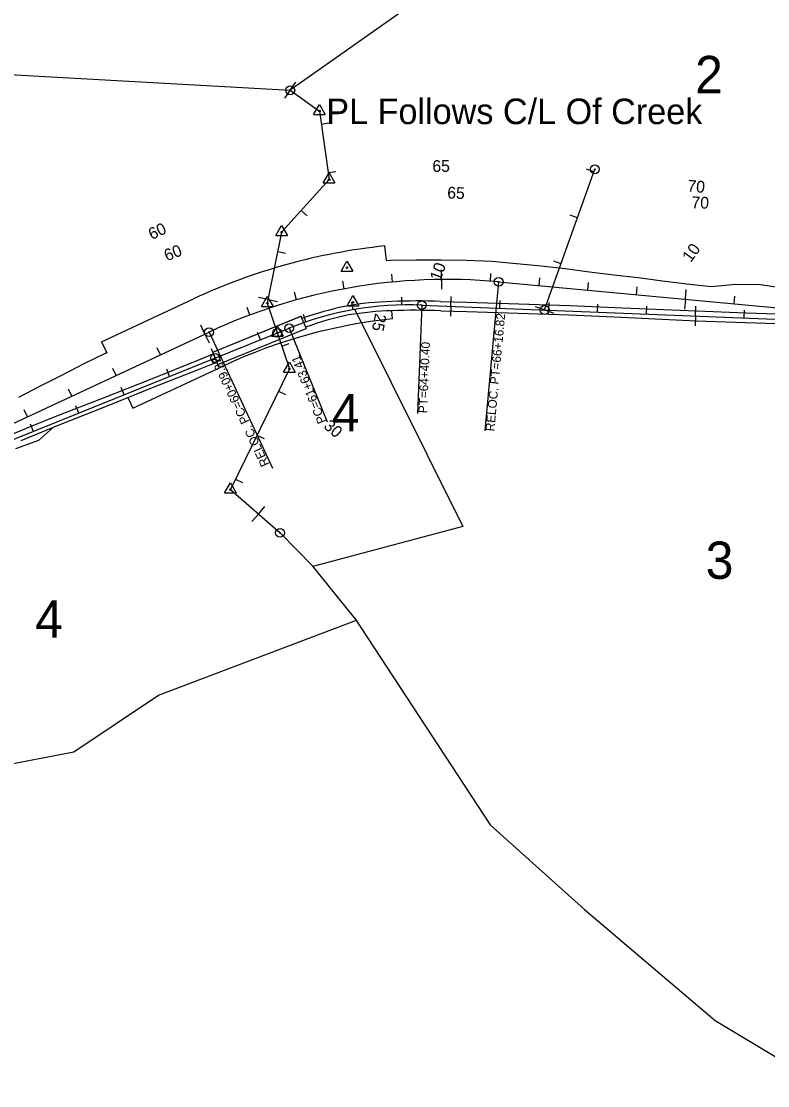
# Model space of a CAD drawing. Extents: x 1965308 to 1970456, y 1116335 to 1119906.
# Drawn here: x 1967302 to 1968827, y 1116335 to 1118511 of the extents above; entities that cross this region are included whole.
import ezdxf

# ---------------------------------------------------------------- set-up
doc = ezdxf.new("R2010")
doc.units = 0
for name, color, linetype in [('RD_EX_Bridge', 7, 'Continuous'), ('RD_EX_DV_Prop', 7, 'Continuous'), ('RD_EX_DV_TX_Prop', 7, 'Continuous'), ('RD_EX_Road', 7, 'Continuous'), ('RD_EX_RW', 7, 'Continuous'), ('RD_HC_Cl', 7, 'Continuous'), ('RD_HC_CL_Rel', 7, 'Continuous'), ('RD_HC_Data', 7, 'Continuous'), ('RD_HC_Data_Rel', 7, 'Continuous'), ('RD_HC_Data_Tic', 7, 'Continuous'), ('RD_HC_Data_Tic_Rel', 7, 'Continuous'), ('RD_HC_TX_Rel_Sta50', 7, 'Continuous'), ('RD_HC_TX_StaOther', 7, 'Continuous'), ('RD_PD_RW', 7, 'Continuous'), ('RD_SMD_Locator', 7, 'Continuous')]:
    doc.layers.add(name, color=color, linetype=linetype)

msp = doc.modelspace()

# ---------------------------------------------------------------- linework, layer by layer
at = {"layer": 'RD_EX_Bridge'}
for p, q in [((1967693.2, 1117834.7), (1967873.6, 1117908.4)), ((1967873.6, 1117908.4), (1967884, 1117883.1)), ((1967703.5, 1117809.4), (1967884, 1117883.1)), ((1967693.2, 1117834.7), (1967703.5, 1117809.4))]:
    msp.add_line(p, q, dxfattribs=at)
at = {"layer": 'RD_EX_DV_Prop'}
for p, q in [((1970021.7, 1119906.4), (1967851.7, 1118370.2)), ((1965856.7, 1118481.4), (1967851.7, 1118370.2)), ((1967983.3, 1117921.8), (1968204.3, 1117478.1)), ((1967830.8, 1117465.4), (1967898.1, 1117396.8)), ((1968204.3, 1117478.1), (1967897.6, 1117396.5)), ((1967983, 1117291.4), (1967898.1, 1117396.8)), ((1967983, 1117291.4), (1968260.1, 1116868.2)), ((1967986.9, 1117286.5), (1967983, 1117291.4)), ((1967582.6, 1117133.3), (1967962.1, 1117277.1)), ((1967962.1, 1117277.1), (1967986.9, 1117286.5)), ((1967409.3, 1117017.8), (1967582.6, 1117133.3)), ((1967101.3, 1116957.5), (1967409.3, 1117017.8)), ((1968260.1, 1116868.2), (1968452.8, 1116695.3)), ((1968452.8, 1116695.3), (1968719.5, 1116468.1)), ((1968719.5, 1116468.1), (1968941.8, 1116334.8))]:
    msp.add_line(p, q, dxfattribs=at)
at = {"layer": 'RD_EX_Road'}
for points in [[(1968158.7, 1117938.6), (1968212.1, 1117937.2), (1968318.8, 1117933.3), (1968422.8, 1117929.9), (1968530.5, 1117925.7)], [(1968530.5, 1117925.7), (1968682, 1117919), (1968783.2, 1117915.4), (1968888.6, 1117911.4), (1968991.2, 1117907.1), (1969092, 1117903.1), (1969191.1, 1117898.7), (1969283.3, 1117895.4)], [(1968159.2, 1117919.4), (1968212.5, 1117918), (1968317.5, 1117914.4), (1968421.5, 1117910.8), (1968527.8, 1117906.4)], [(1968527.8, 1117906.4), (1968680.8, 1117899.1), (1968781.7, 1117895.4), (1968887.9, 1117891.8), (1968988.7, 1117888.2), (1969090.1, 1117882.8), (1969189.3, 1117879), (1969282.9, 1117875.4)], [(1966769.5, 1117457.5), (1966870.2, 1117497.3), (1966971.2, 1117539), (1967071.1, 1117580.2), (1967172.6, 1117621.5), (1967270.8, 1117661.7), (1967321.1, 1117682.6), (1967371.5, 1117702.9), (1967470.3, 1117741.6), (1967566.7, 1117779.5), (1967661.2, 1117817.5), (1967694.4, 1117831.2)], [(1967302.2, 1117654.1), (1967379.3, 1117686.2), (1967476.1, 1117724.4), (1967573.9, 1117763.5), (1967667.7, 1117800.7), (1967701.6, 1117814)]]:
    msp.add_lwpolyline(points, dxfattribs=at)
for centre, radius, start, end in [((1968104.9, 1117261.1), 682.1, 101.7162, 109.6396), ((1968075.1, 1117320.6), 617.9, 91.4965, 100.1295), ((1968111.4, 1116608.6), 1330.8, 87.9632, 92.259), ((1968107.6, 1116504.3), 1416, 87.9115, 91.9598), ((1968080.6, 1117363), 558.7, 101.3479, 110.7006), ((1968080.7, 1117246.5), 673.3, 91.837, 99.4057)]:
    msp.add_arc(centre, radius, start, end, dxfattribs=at)
at = {"layer": 'RD_EX_RW'}
for p, q in [((1967693.2, 1117834.7), (1967873.9, 1117908.5)), ((1967875.7, 1117903.5), (1967873.9, 1117908.5)), ((1967703.5, 1117809.4), (1967884, 1117883.1)), ((1967883.1, 1117885.6), (1967884, 1117883.1)), ((1967694.6, 1117831.3), (1967693.2, 1117834.7)), ((1967701.6, 1117814), (1967703.5, 1117809.4))]:
    msp.add_line(p, q, dxfattribs=at)
for points in [[(1968059, 1117938.4), (1968058.9, 1117938.4), (1968058.9, 1117938.4)], [(1968158.7, 1117938.6), (1968212.1, 1117937.2), (1968318.8, 1117933.3), (1968422.8, 1117929.9), (1968530.5, 1117925.7)], [(1968530.5, 1117925.7), (1968682, 1117919), (1968783.2, 1117915.4), (1968888.6, 1117911.4), (1968991.2, 1117907.1), (1969092, 1117903.1), (1969191.1, 1117898.7), (1969283.3, 1117895.4)], [(1967970.6, 1117910.8), (1967970.7, 1117910.8), (1967970.8, 1117910.8)], [(1968159.2, 1117919.4), (1968212.5, 1117918), (1968317.5, 1117914.4), (1968421.5, 1117910.8), (1968527.8, 1117906.4)], [(1968527.8, 1117906.4), (1968680.8, 1117899.1), (1968781.7, 1117895.4), (1968887.9, 1117891.8), (1968988.7, 1117888.2), (1969090.1, 1117882.8), (1969189.3, 1117879), (1969282.9, 1117875.4)], [(1966769.5, 1117457.5), (1966870.2, 1117497.3), (1966971.2, 1117539), (1967071.1, 1117580.2), (1967172.6, 1117621.5), (1967270.8, 1117661.7), (1967321.1, 1117682.6), (1967371.5, 1117702.9), (1967470.3, 1117741.6), (1967566.7, 1117779.5), (1967661.2, 1117817.5), (1967694.6, 1117831.3)], [(1967302.2, 1117654.1), (1967379.3, 1117686.2), (1967476.1, 1117724.4), (1967573.9, 1117763.5), (1967667.7, 1117800.7), (1967701.6, 1117814)]]:
    msp.add_lwpolyline(points, dxfattribs=at)
for centre, radius, start, end in [((1968104.9, 1117261.1), 682.1, 101.7162, 109.6396), ((1968075.1, 1117320.6), 617.9, 91.4996, 100.1295), ((1968111.4, 1116608.6), 1330.8, 87.9632, 92.2576), ((1968107.6, 1116504.3), 1416, 87.9115, 91.9598), ((1968080.6, 1117363), 558.7, 101.3567, 110.7006), ((1968080.7, 1117246.5), 673.3, 91.837, 99.3984)]:
    msp.add_arc(centre, radius, start, end, dxfattribs=at)
at = {"layer": 'RD_HC_Cl'}
for p, q in [((1967851.7, 1118370.2), (1967911.4, 1118327.7)), ((1967911.4, 1118327.7), (1967931.1, 1118187.5)), ((1968371.4, 1117921), (1968474, 1118208.6)), ((1967931.1, 1118187.5), (1967834, 1118080)), ((1967834, 1118080), (1967804.8, 1117934.9)), ((1967804.8, 1117934.9), (1967849.8, 1117800.6)), ((1968120.3, 1117930.9), (1969279, 1117884.9)), ((1966770.7, 1117448.1), (1967849.5, 1117883.9)), ((1967849.8, 1117800.6), (1967729.3, 1117553.7)), ((1967729.3, 1117553.7), (1967830.8, 1117465.4))]:
    msp.add_line(p, q, dxfattribs=at)
msp.add_arc((1968094.4, 1117277.5), 653.9, 87.7266, 111.9958, dxfattribs=at)
at = {"layer": 'RD_HC_CL_Rel'}
for p, q in [((1968277.4, 1117978.5), (1969226.4, 1117889.9)), ((1966858.9, 1117489.3), (1967685.7, 1117875.7))]:
    msp.add_line(p, q, dxfattribs=at)
msp.add_arc((1968170.8, 1116837.5), 1145.9, 84.6661, 115.0463, dxfattribs=at)
at = {"layer": 'RD_HC_Data'}
for p, q in [((1967899.5, 1118320.8), (1967911.4, 1118341.4)), ((1967911.4, 1118341.4), (1967923.3, 1118320.8)), ((1967899.5, 1118320.8), (1967923.3, 1118320.8)), ((1967919.1, 1118180.7), (1967931.1, 1118201.3)), ((1967931.1, 1118201.3), (1967943, 1118180.7)), ((1967919.1, 1118180.7), (1967943, 1118180.7)), ((1967822.1, 1118073.1), (1967834, 1118093.7)), ((1967822.1, 1118073.1), (1967845.9, 1118073.1)), ((1967834, 1118093.7), (1967845.9, 1118073.1)), ((1967792.9, 1117928), (1967804.8, 1117948.6)), ((1967804.8, 1117948.6), (1967816.7, 1117928)), ((1967967.9, 1117929.6), (1967979.8, 1117950.3)), ((1967979.8, 1117950.3), (1967991.7, 1117929.6)), ((1967792.9, 1117928), (1967816.7, 1117928)), ((1967967.9, 1117929.6), (1967991.7, 1117929.6)), ((1968120.3, 1117930.9), (1968111.5, 1117709)), ((1967813.3, 1117867.2), (1967825.2, 1117887.8)), ((1967825.2, 1117887.8), (1967837.1, 1117867.2)), ((1967849.5, 1117883.9), (1967926.8, 1117692.4)), ((1967813.3, 1117867.2), (1967837.1, 1117867.2)), ((1967837.9, 1117793.7), (1967849.8, 1117814.4)), ((1967849.8, 1117814.4), (1967861.7, 1117793.7)), ((1967837.9, 1117793.7), (1967861.7, 1117793.7)), ((1967717.4, 1117546.8), (1967729.3, 1117567.4)), ((1967729.3, 1117567.4), (1967741.2, 1117546.8)), ((1967717.4, 1117546.8), (1967741.2, 1117546.8))]:
    msp.add_line(p, q, dxfattribs=at)
for centre, radius in [((1967851.7, 1118370.2), 9), ((1967851.7, 1118370.2), 0.845), ((1967911.4, 1118327.7), 1.59), ((1968474, 1118208.6), 9), ((1968474, 1118208.6), 0.845), ((1967931.1, 1118187.5), 1.59), ((1967834, 1118080), 1.59), ((1967804.8, 1117934.9), 1.59), ((1967979.8, 1117936.5), 1.59), ((1968120.3, 1117930.9), 9), ((1968120.3, 1117930.9), 0.845), ((1968371.4, 1117921), 9), ((1968371.4, 1117921), 9), ((1968371.4, 1117921), 0.845), ((1968371.4, 1117921), 0.845), ((1967825.2, 1117874.1), 9), ((1967849.5, 1117883.9), 9), ((1967849.5, 1117883.9), 0.845), ((1967825.2, 1117874.1), 1.59), ((1967825.2, 1117874.1), 0.845), ((1967698.1, 1117822.7), 9), ((1967698.1, 1117822.7), 0.845), ((1967849.8, 1117800.6), 1.59), ((1967729.3, 1117553.7), 1.59), ((1967830.8, 1117465.4), 9), ((1967830.8, 1117465.4), 0.845)]:
    msp.add_circle(centre, radius, dxfattribs=at)
at = {"layer": 'RD_HC_Data_Rel'}
for p, q in [((1967955.7, 1118000.5), (1967967.6, 1118021.1)), ((1967967.6, 1118021.1), (1967979.5, 1118000.5)), ((1967955.7, 1118000.5), (1967979.5, 1118000.5)), ((1968277.4, 1117978.5), (1968248.9, 1117674.2)), ((1967685.7, 1117875.7), (1967815.6, 1117597.7))]:
    msp.add_line(p, q, dxfattribs=at)
for centre, radius in [((1967967.6, 1118007.4), 1.59), ((1968277.4, 1117978.5), 9), ((1968277.4, 1117978.5), 0.845), ((1967685.7, 1117875.7), 9), ((1967685.7, 1117875.7), 0.845)]:
    msp.add_circle(centre, radius, dxfattribs=at)
at = {"layer": 'RD_HC_Data_Tic'}
for p, q in [((1967851.7, 1118370.2), (1967863.4, 1118386.5)), ((1967851.7, 1118370.2), (1967840.1, 1118354)), ((1967915.1, 1118301.2), (1967930.9, 1118303.4)), ((1967929, 1118202.2), (1967944.8, 1118204.4)), ((1968472.1, 1118203.5), (1968457.1, 1118208.9)), ((1967874, 1118124.2), (1967885.9, 1118113.5)), ((1968438.5, 1118109.4), (1968423.5, 1118114.7)), ((1967826.1, 1118040.4), (1967841.7, 1118037.2)), ((1968404.9, 1118015.2), (1968389.9, 1118020.5)), ((1967806.3, 1117942.4), (1967786.7, 1117946.3)), ((1967806.3, 1117942.4), (1967825.9, 1117938.4)), ((1968079.9, 1117931.3), (1968079.6, 1117947.3)), ((1968179.9, 1117928.6), (1968180.7, 1117948.6)), ((1967980.5, 1117921.5), (1967977.7, 1117937.2)), ((1968179.9, 1117928.6), (1968179.1, 1117908.6)), ((1968279.8, 1117924.6), (1968280.4, 1117940.6)), ((1968371.4, 1117921), (1968352.5, 1117927.7)), ((1968371.4, 1117921), (1968390.2, 1117914.3)), ((1968379.7, 1117920.6), (1968380.4, 1117936.6)), ((1968479.6, 1117916.7), (1968480.3, 1117932.7)), ((1968579.6, 1117912.7), (1968580.2, 1117928.7)), ((1968679.5, 1117908.7), (1968680.3, 1117928.7)), ((1968779.4, 1117904.8), (1968780, 1117920.8)), ((1967883.8, 1117896.6), (1967878.6, 1117911.8)), ((1968679.5, 1117908.7), (1968678.7, 1117888.8)), ((1967790.7, 1117860.1), (1967784.7, 1117874.9)), ((1967698, 1117822.7), (1967690.5, 1117841.2)), ((1967834.2, 1117847.3), (1967849.3, 1117852.4)), ((1967698, 1117822.7), (1967705.4, 1117804.1)), ((1967605.2, 1117785.2), (1967599.2, 1117800)), ((1967512.5, 1117747.7), (1967506.5, 1117762.6)), ((1967827.6, 1117755), (1967841.9, 1117748)), ((1967419.8, 1117710.3), (1967413.8, 1117725.1)), ((1967327.1, 1117672.8), (1967321.1, 1117687.7)), ((1967783.7, 1117665.1), (1967798.1, 1117658.1)), ((1967739.8, 1117575.2), (1967754.2, 1117568.2)), ((1967786.6, 1117503.8), (1967799.8, 1117518.9)), ((1967786.6, 1117503.8), (1967773.5, 1117488.7))]:
    msp.add_line(p, q, dxfattribs=at)
at = {"layer": 'RD_HC_Data_Tic_Rel'}
for p, q in [((1968060.9, 1117978.1), (1968059.3, 1117994.1)), ((1968160.7, 1117983.4), (1968160.5, 1118003.4)), ((1968260.6, 1117979.9), (1968261.8, 1117995.9)), ((1968360.2, 1117970.7), (1968361.7, 1117986.7)), ((1967961.9, 1117964.2), (1967958.9, 1117979.9)), ((1968160.7, 1117983.4), (1968160.9, 1117963.4)), ((1968459.7, 1117961.4), (1968461.2, 1117977.4)), ((1968559.3, 1117952.1), (1968560.8, 1117968.1)), ((1967864.5, 1117941.7), (1967860.2, 1117957.1)), ((1968658.9, 1117942.8), (1968657, 1117922.9)), ((1968658.9, 1117942.8), (1968660.7, 1117962.8)), ((1968758.4, 1117933.5), (1968759.9, 1117949.5)), ((1967769.4, 1117910.8), (1967763.8, 1117925.8)), ((1967677.4, 1117871.8), (1967668.9, 1117889.9)), ((1967677.4, 1117871.8), (1967685.8, 1117853.7)), ((1967586.8, 1117829.4), (1967580, 1117843.9)), ((1967496.2, 1117787.1), (1967489.4, 1117801.6)), ((1967405.6, 1117744.8), (1967398.8, 1117759.3)), ((1967315, 1117702.4), (1967308.2, 1117716.9))]:
    msp.add_line(p, q, dxfattribs=at)
at = {"layer": 'RD_PD_RW'}
for p, q in [((1968048.3, 1118022.1), (1968045.2, 1118051.9)), ((1968048.3, 1118022.1), (1968056.6, 1118022.8)), ((1968056.6, 1118022.8), (1968108.6, 1118023.3)), ((1968108.6, 1118023.3), (1968160.3, 1118023.6)), ((1968160.3, 1118023.6), (1968212.1, 1118023)), ((1968212.1, 1118023), (1968263.8, 1118020.6)), ((1968263.8, 1118020.6), (1968314.2, 1118016.3)), ((1968314.2, 1118016.3), (1968364, 1118011.2)), ((1968364, 1118011.2), (1968413.7, 1118005.8)), ((1968413.7, 1118005.8), (1968463.3, 1117999.1)), ((1968463.3, 1117999.1), (1968512.9, 1117993.1)), ((1968512.9, 1117993.1), (1968562.6, 1117987.5)), ((1968562.6, 1117987.5), (1968612.2, 1117980.7)), ((1968612.2, 1117980.7), (1968661.8, 1117974.4)), ((1968661.8, 1117974.4), (1968711.4, 1117968.9)), ((1968711.4, 1117968.9), (1968762, 1117973.5)), ((1968762, 1117973.5), (1968812.3, 1117973.2)), ((1968812.3, 1117973.2), (1968861.9, 1117965.3)), ((1967466.2, 1117855.9), (1967654, 1117943.6)), ((1968060.6, 1117902.7), (1968058.9, 1117919.5)), ((1967466.2, 1117855.9), (1967476.8, 1117833.3)), ((1967475, 1117832.4), (1967476.8, 1117833.3)), ((1967475, 1117832.4), (1967430, 1117810.6)), ((1967430, 1117810.6), (1967385.5, 1117787.6)), ((1967529.7, 1117720), (1967717.5, 1117807.7)), ((1967385.5, 1117787.6), (1967340.9, 1117765)), ((1967340.9, 1117765), (1967296.4, 1117742.1)), ((1967519.5, 1117741.8), (1967529.7, 1117720)), ((1967367.7, 1117681.4), (1967337.6, 1117654.3)), ((1967337.6, 1117654.3), (1967290.1, 1117637.3))]:
    msp.add_line(p, q, dxfattribs=at)
for radius in [1220.9, 1070.9]:
    msp.add_arc((1968170.8, 1116837.5), radius, 95.9072, 115.0463, dxfattribs=at)
at = {"layer": 'RD_SMD_Locator'}
for centre in [(1967851.7, 1118370.2), (1967911.4, 1118327.7), (1968474, 1118208.6), (1967931.1, 1118187.5), (1967834, 1118080), (1967804.8, 1117934.9), (1967979.8, 1117936.5), (1968120.3, 1117930.9), (1968371.4, 1117921), (1968371.4, 1117921), (1967849.5, 1117883.9), (1967825.2, 1117874.1), (1967825.2, 1117874.1), (1967698.1, 1117822.7), (1967849.8, 1117800.6), (1967729.3, 1117553.7), (1967830.8, 1117465.4)]:
    msp.add_circle(centre, 0.003, dxfattribs=at)

# ---------------------------------------------------------------- texts
at = {"layer": 'RD_EX_DV_TX_Prop'}
for s, height, p in [('2', 76.4, (1968678.8, 1118364.1)), ('PL Follows C/L Of Creek', 52.212, (1967925.3, 1118301)), ('4', 76.4, (1967936.6, 1117673)), ('3', 76.4, (1968700.4, 1117371.1)), ('4', 76.4, (1967330.4, 1117251.2))]:
    msp.add_text(s, height=height, dxfattribs=at).set_placement(p)
at = {"layer": 'RD_HC_Data'}
for s, rotation, p in [('PT=64+40.40', 87.7266, (1968131.5, 1117709.6)), ('PC=61+63.41', 111.9958, (1967925.5, 1117692.8))]:
    msp.add_text(s, height=18, rotation=rotation, dxfattribs=at).set_placement(p)
at = {"layer": 'RD_HC_Data_Rel'}
for s, rotation, p in [('RELOC. PT=66+16.82', 84.6661, (1968268.5, 1117672.3)), ('RELOC. PC=60+09.22', 115.0463, (1967809.4, 1117605.7))]:
    msp.add_text(s, height=18, rotation=rotation, dxfattribs=at).set_placement(p)
at = {"layer": 'RD_HC_TX_Rel_Sta50'}
for s, rotation, p in [('65', 0.5072, (1968142.2, 1118203.2)), ('70', 354.6661, (1968662.3, 1118163.5)), ('60', 25.0463, (1967568.7, 1118063.8))]:
    msp.add_text(s, height=24, rotation=rotation, dxfattribs=at).set_placement(p)
at = {"layer": 'RD_HC_TX_StaOther'}
for s, rotation, p in [('65', 357.7266, (1968172.1, 1118149.1)), ('70', 357.7266, (1968671.1, 1118129.3)), ('60', 21.9958, (1967599.7, 1118020.2)), ('10', 54.0772, (1968670, 1118016.9)), ('10', 70.3698, (1968158.4, 1117978.8)), ('25', 258.6104, (1968025.3, 1117915.1)), ('30', 318.9993, (1967918.1, 1117681.1))]:
    msp.add_text(s, height=24, rotation=rotation, dxfattribs=at).set_placement(p)

doc.saveas('drawing.dxf')
